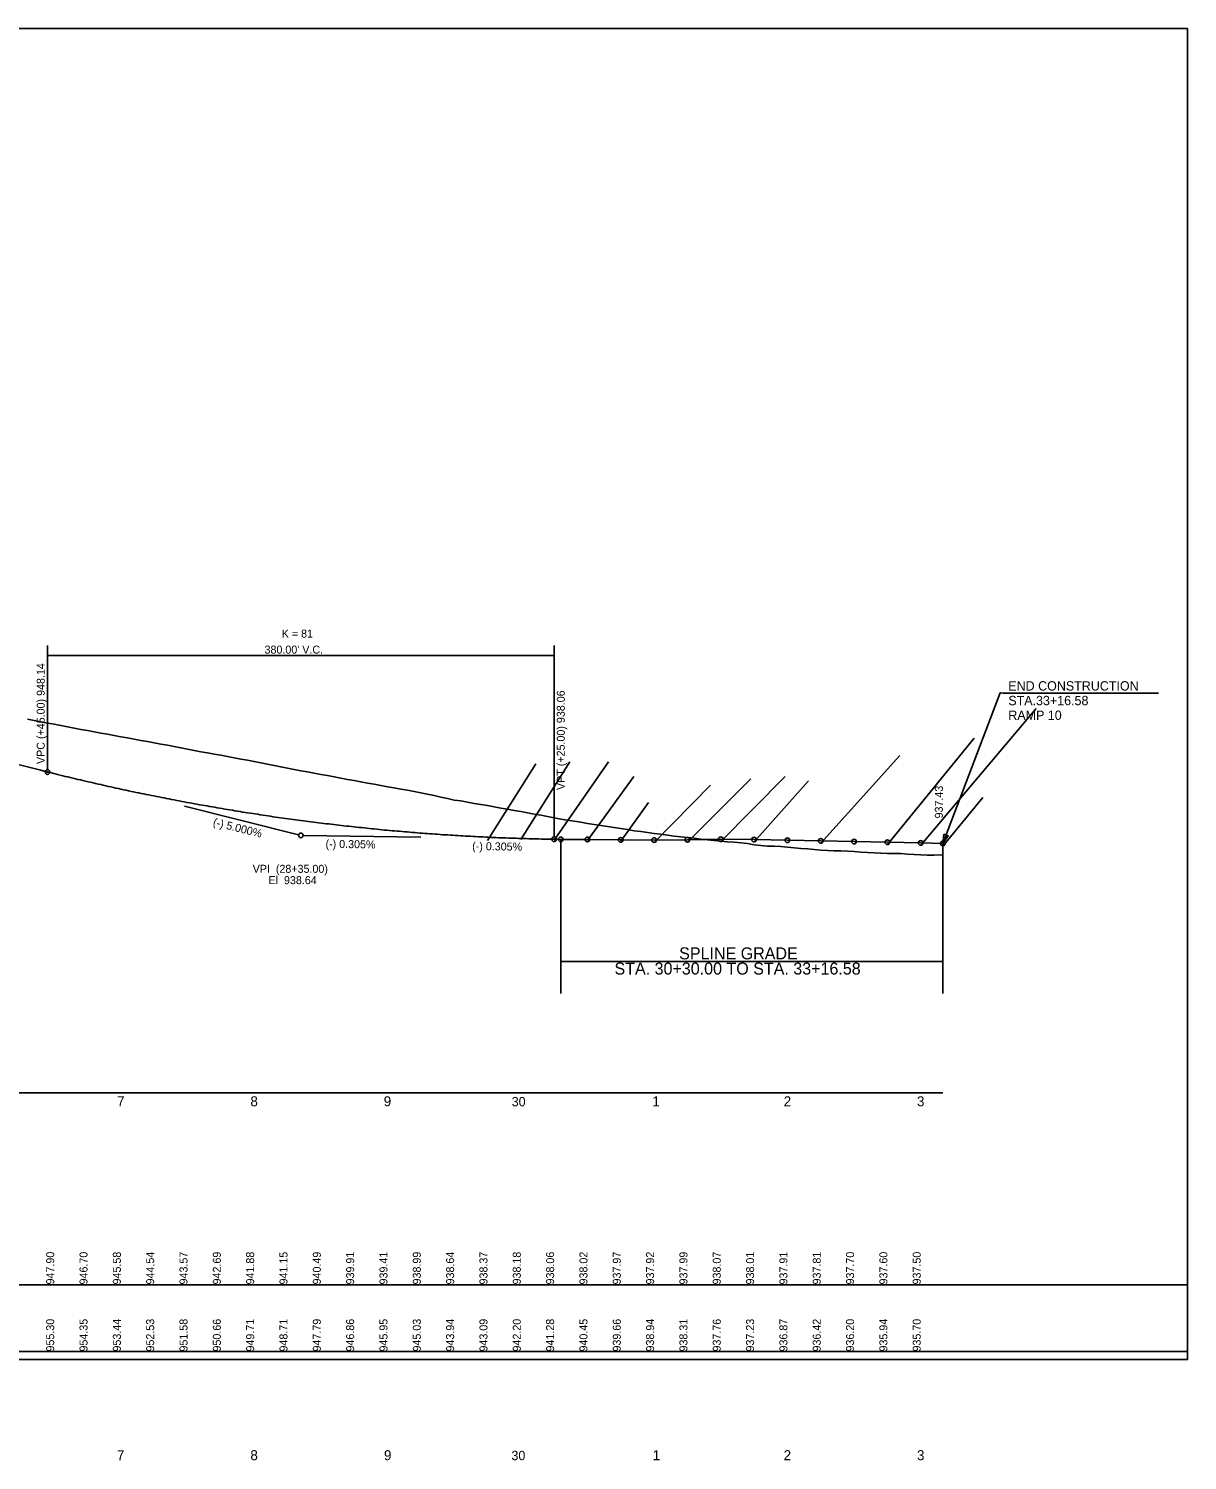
# Model space of a CAD drawing. Extents: x 111 to 16974612, y 6 to 12550779.
# Drawn here: x 16973743 to 16974612, y 12549503 to 12550577 of the extents above; entities that cross this region are included whole.
import ezdxf

# ---------------------------------------------------------------- set-up
doc = ezdxf.new("R2010")
doc.units = 0
for name, color, linetype in [('Default', 7, 'Continuous'), ('RD_DDB_GradeTX', 7, 'Continuous'), ('RD_DDB_PI', 7, 'Continuous'), ('RD_DDB_Profile_EX', 7, 'Continuous'), ('RD_DDB_Profile_Lbl', 7, 'Continuous'), ('RD_DDB_Profile_PR', 7, 'Continuous'), ('RD_DDB_StaTX', 7, 'Continuous'), ('RD_DDB_StripGrade', 7, 'Continuous'), ('RD_DDB_StripGrade_EX', 7, 'Continuous'), ('RD_DDB_StripGrade_PR', 7, 'Continuous'), ('RD_DDB_VCLbl', 7, 'Continuous'), ('RD_GPK_Profile_Cell', 7, 'Continuous'), ('RD_Sketch1', 7, 'Continuous'), ('RD_TX_Profile', 7, 'Continuous')]:
    doc.layers.add(name, color=color, linetype=linetype)

msp = doc.modelspace()

# ---------------------------------------------------------------- linework, layer by layer
at = {"layer": 'Default'}
msp.add_lwpolyline([(16973112.2, 12549578.8), (16974612.2, 12549578.8), (16974612.2, 12550577), (16973112.2, 12550577)], close=True, dxfattribs=at)
at = {"layer": 'RD_DDB_PI'}
for p, q in [((16973859.9, 12549993.8), (16973945.5, 12549972.4)), ((16974037.2, 12549970.6), (16973949, 12549972))]:
    msp.add_line(p, q, dxfattribs=at)
for centre in [(16973947.2, 12549972), (16974142.2, 12549969), (16974162.2, 12549968.9), (16974187.2, 12549968.6), (16974212.2, 12549968.4), (16974237.2, 12549968.7), (16974262.2, 12549969.1), (16974287.2, 12549968.8), (16974312.2, 12549968.3), (16974337.2, 12549967.8), (16974362.2, 12549967.3), (16974387.2, 12549966.8), (16974412.2, 12549966.3), (16974428.8, 12549965.9)]:
    msp.add_circle(centre, 1.75, dxfattribs=at)
at = {"layer": 'RD_DDB_Profile_EX'}
for points in [[(16973742.2, 12550059.1), (16973747.2, 12550058.1), (16973752.2, 12550057.2), (16973757.2, 12550056.2), (16973762.2, 12550055.3), (16973767.2, 12550054.4), (16973772.2, 12550053.4), (16973777.2, 12550052.5), (16973782.2, 12550051.5), (16973787.2, 12550050.6), (16973792.2, 12550049.6), (16973797.2, 12550048.7), (16973802.2, 12550047.8), (16973807.2, 12550046.9), (16973812.2, 12550046), (16973817.2, 12550045.1), (16973822.2, 12550044.1), (16973827.2, 12550043.2), (16973832.2, 12550042.3), (16973837.2, 12550041.4), (16973842.2, 12550040.5), (16973847.2, 12550039.6), (16973852.2, 12550038.6), (16973857.2, 12550037.7), (16973862.2, 12550036.7), (16973867.2, 12550035.7), (16973872.2, 12550034.7), (16973877.2, 12550033.9), (16973882.2, 12550033), (16973887.2, 12550032.1), (16973892.2, 12550031.2), (16973897.2, 12550030.2), (16973902.2, 12550029.2), (16973907.2, 12550028.3), (16973912.2, 12550027.3), (16973917.2, 12550026.4), (16973922.2, 12550025.3), (16973927.2, 12550024.3), (16973932.2, 12550023.3), (16973937.2, 12550022.4), (16973942.2, 12550021.4), (16973947.2, 12550020.5), (16973952.2, 12550019.6), (16973957.2, 12550018.6), (16973962.2, 12550017.7), (16973967.2, 12550016.8), (16973972.2, 12550015.9), (16973977.2, 12550015), (16973982.2, 12550014), (16973987.2, 12550013.1), (16973992.2, 12550012.1), (16973997.2, 12550011.2), (16974002.2, 12550010.3), (16974007.2, 12550009.4), (16974012.2, 12550008.5), (16974017.2, 12550007.7), (16974022.2, 12550006.7), (16974027.2, 12550005.8), (16974032.2, 12550004.9), (16974037.2, 12550003.9), (16974042.2, 12550002.8), (16974047.2, 12550001.8), (16974052.2, 12550000.7), (16974057.2, 12549999.7), (16974062.2, 12549998.5), (16974067.2, 12549997.9), (16974072.2, 12549997), (16974077.2, 12549996), (16974082.2, 12549995.1), (16974087.2, 12549994.3), (16974092.2, 12549993.4), (16974097.2, 12549992.5), (16974102.2, 12549991.6), (16974107.2, 12549990.7), (16974112.2, 12549989.8)], [(16974112.2, 12549989.8), (16974117.2, 12549988.9), (16974122.2, 12549988), (16974127.2, 12549987.1), (16974132.2, 12549986.2), (16974137.2, 12549985.2), (16974142.2, 12549984.2), (16974147.2, 12549983.3), (16974152.2, 12549982.6), (16974157.2, 12549981.8), (16974162.2, 12549981), (16974167.2, 12549980.2), (16974172.2, 12549979.5), (16974177.2, 12549978.7), (16974182.2, 12549977.8), (16974187.2, 12549977.1), (16974192.2, 12549976.3), (16974197.2, 12549975.5), (16974202.2, 12549974.8), (16974207.2, 12549974.2), (16974212.2, 12549973.5), (16974217.2, 12549972.8), (16974222.2, 12549972.1), (16974227.2, 12549971.5), (16974232.2, 12549970.9), (16974237.2, 12549970.3), (16974242.2, 12549969.8), (16974247.2, 12549969.2), (16974252.2, 12549968.7), (16974257.2, 12549968.1), (16974262.2, 12549967.6), (16974267.2, 12549967.2), (16974272.2, 12549966.9), (16974277.2, 12549966.5), (16974282.2, 12549965.8), (16974287.2, 12549965), (16974292.2, 12549964.4), (16974297.2, 12549964), (16974302.2, 12549963.8), (16974307.2, 12549963.6), (16974312.2, 12549963.1), (16974317.2, 12549962.6), (16974322.2, 12549962.2), (16974327.2, 12549961.8), (16974332.2, 12549961.3), (16974337.2, 12549960.9), (16974342.2, 12549960.6), (16974347.2, 12549960.4), (16974352.2, 12549960.3), (16974357.2, 12549960.1), (16974362.2, 12549959.8), (16974367.2, 12549959.4), (16974372.2, 12549959.1), (16974377.2, 12549958.9), (16974382.2, 12549958.6), (16974387.2, 12549958.5), (16974392.2, 12549958.4), (16974397.2, 12549958.3), (16974402.2, 12549958), (16974407.2, 12549957.7), (16974412.2, 12549957.3), (16974417.2, 12549957.1), (16974422.2, 12549957.2), (16974427.2, 12549957.3), (16974428.8, 12549957.2)]]:
    msp.add_lwpolyline(points, dxfattribs=at)
at = {"layer": 'RD_DDB_Profile_Lbl'}
for p, q in [((16973112.2, 12549634.9), (16974612.2, 12549634.9)), ((16973112.2, 12549584.9), (16974612.2, 12549584.9))]:
    msp.add_line(p, q, dxfattribs=at)
at = {"layer": 'RD_DDB_Profile_PR'}
for p, q in [((16973392.2, 12550110.8), (16973762.2, 12550018.3)), ((16973752.2, 12550020.8), (16973757.2, 12550019.5)), ((16974137.2, 12549969.1), (16974142.2, 12549969)), ((16974142.2, 12549969), (16974162.2, 12549968.9)), ((16974162.2, 12549968.9), (16974187.2, 12549968.6)), ((16974187.2, 12549968.6), (16974212.2, 12549968.4)), ((16974212.2, 12549968.4), (16974237.2, 12549968.7)), ((16974237.2, 12549968.7), (16974262.2, 12549969.1)), ((16974262.2, 12549969.1), (16974287.2, 12549968.8)), ((16974287.2, 12549968.8), (16974312.2, 12549968.3)), ((16974312.2, 12549968.3), (16974337.2, 12549967.8)), ((16974337.2, 12549967.8), (16974362.2, 12549967.3)), ((16974362.2, 12549967.3), (16974387.2, 12549966.8)), ((16974387.2, 12549966.8), (16974412.2, 12549966.3)), ((16974412.2, 12549966.3), (16974428.8, 12549965.9))]:
    msp.add_line(p, q, dxfattribs=at)
msp.add_spline([(16973757.2, 12550019.5), (16973764.8, 12550017.6), (16973772.4, 12550015.8), (16973780, 12550014), (16973787.6, 12550012.2), (16973795.2, 12550010.5), (16973802.8, 12550008.7), (16973810.4, 12550007.1), (16973818, 12550005.4), (16973825.6, 12550003.8), (16973833.2, 12550002.3), (16973840.8, 12550000.8), (16973848.4, 12549999.3), (16973856, 12549997.8), (16973863.6, 12549996.4), (16973871.2, 12549995), (16973878.8, 12549993.7), (16973886.4, 12549992.4), (16973894, 12549991.1), (16973901.6, 12549989.8), (16973909.2, 12549988.6), (16973916.8, 12549987.5), (16973924.4, 12549986.3), (16973932, 12549985.2), (16973939.6, 12549984.2), (16973947.2, 12549983.2), (16973954.8, 12549982.2), (16973962.4, 12549981.2), (16973970, 12549980.3), (16973977.6, 12549979.4), (16973985.2, 12549978.6), (16973992.8, 12549977.8), (16974000.4, 12549977), (16974008, 12549976.2), (16974015.6, 12549975.5), (16974023.2, 12549974.9), (16974030.8, 12549974.2), (16974038.4, 12549973.6), (16974046, 12549973.1), (16974053.6, 12549972.5), (16974061.2, 12549972.1), (16974068.8, 12549971.6), (16974076.4, 12549971.2), (16974084, 12549970.8), (16974091.6, 12549970.4), (16974099.2, 12549970.1), (16974106.8, 12549969.9), (16974114.4, 12549969.6), (16974122, 12549969.4), (16974129.6, 12549969.2), (16974137.2, 12549969.1)], degree=3, dxfattribs=at)
at = {"layer": 'RD_DDB_StripGrade'}
for p, q in [((16974142.2, 12549853.3), (16974142.2, 12549969)), ((16974428.8, 12549853.3), (16974428.8, 12549965.9)), ((16974142.2, 12549877.4), (16974428.8, 12549877.4))]:
    msp.add_line(p, q, dxfattribs=at)
at = {"layer": 'RD_DDB_VCLbl'}
for p, q in [((16973757.2, 12550114.5), (16973757.2, 12550021.3)), ((16974137.2, 12550114.5), (16974137.2, 12549970.9)), ((16973757.2, 12550107), (16974137.2, 12550107))]:
    msp.add_line(p, q, dxfattribs=at)
for centre in [(16973757.2, 12550019.5), (16974137.2, 12549969.1), (16974142.2, 12549969)]:
    msp.add_circle(centre, 1.75, dxfattribs=at)
at = {"layer": 'RD_GPK_Profile_Cell'}
msp.add_line((16973112.2, 12549778.8), (16974428.8, 12549778.8), dxfattribs=at)
at = {"layer": 'RD_Sketch1'}
for p, q in [((16974412.2, 12549964.6), (16974498.7, 12550067.2)), ((16974387.2, 12549965.1), (16974452.4, 12550044.8)), ((16974087.2, 12549968.2), (16974123.6, 12550025.6)), ((16974112.2, 12549968.8), (16974149.1, 12550027.2)), ((16974137.2, 12549968.5), (16974177.9, 12550027.2)), ((16974337.2, 12549966.1), (16974396.6, 12550032)), ((16974162.2, 12549968.1), (16974197, 12550016.1)), ((16974237.2, 12549967), (16974284.8, 12550014.5)), ((16974262.2, 12549967.4), (16974310.4, 12550016.1)), ((16974287.2, 12549967.2), (16974327.9, 12550012.9)), ((16974212.2, 12549966.7), (16974254.5, 12550009.7)), ((16974428.8, 12549963.9), (16974458.8, 12550000.5)), ((16974187.2, 12549967.7), (16974207.9, 12549996.6))]:
    msp.add_line(p, q, dxfattribs=at)
at = {"layer": 'RD_TX_Profile'}
msp.add_line((16974590.5, 12550078.6), (16974473.9, 12550078.6), dxfattribs=at)
msp.add_lwpolyline([(16974473.9, 12550078.6), (16974471.9, 12550079), (16974428.8, 12549965.9)], dxfattribs=at)
msp.add_lwpolyline([(16974429.5, 12549972.9), (16974428.8, 12549965.9), (16974432.9, 12549971.6)], close=True, dxfattribs=at)

# ---------------------------------------------------------------- texts
at = {"layer": 'RD_DDB_GradeTX'}
for s, rotation, p in [('(-) 5.000%', 345.9638, (16973880.9, 12549979.3)), ('(-) 0.305%', 359.127, (16973965.7, 12549962.7)), ('(-) 0.305%', 359.127, (16974075.7, 12549961))]:
    msp.add_text(s, height=6, rotation=rotation, dxfattribs=at).set_placement(p)
at = {"layer": 'RD_DDB_PI'}
msp.add_text('937.43', height=6, rotation=90, dxfattribs=at).set_placement((16974428.8, 12549984.7))
for s, p in [('VPI  (28+35.00)', (16973911.1, 12549943.9)), ('El  938.64', (16973923, 12549935.4))]:
    msp.add_text(s, height=6, dxfattribs=at).set_placement(p)
at = {"layer": 'RD_DDB_StaTX'}
for s, height, p in [('7', 7.5, (16973809.4, 12549768.8)), ('8', 7.5, (16973909.4, 12549768.8)), ('9', 7.5, (16974009.4, 12549768.8)), ('30', 7, (16974105.4, 12549768.8)), ('1', 7.5, (16974210.9, 12549768.8)), ('2', 7.5, (16974309.4, 12549768.8)), ('3', 7.5, (16974409.4, 12549768.8)), ('7', 7.5, (16973809.3, 12549503.4)), ('8', 7.5, (16973909.4, 12549503.4)), ('9', 7.5, (16974009.6, 12549503.4)), ('30', 7, (16974105.2, 12549503.4)), ('1', 7.5, (16974211.2, 12549503.4)), ('2', 7.5, (16974309.4, 12549503.4)), ('3', 7.5, (16974409.4, 12549503.4))]:
    msp.add_text(s, height=height, dxfattribs=at).set_placement(p)
at = {"layer": 'RD_DDB_StripGrade'}
for s, p in [('SPLINE GRADE', (16974231, 12549879)), ('STA. 30+30.00 TO STA. 33+16.58', (16974182.5, 12549867.6))]:
    msp.add_text(s, height=9, dxfattribs=at).set_placement(p)
at = {"layer": 'RD_DDB_StripGrade_EX'}
for s, p in [('955.30', (16973762.2, 12549584.9)), ('954.35', (16973787.2, 12549584.9)), ('953.44', (16973812.2, 12549584.9)), ('952.53', (16973837.2, 12549584.9)), ('951.58', (16973862.2, 12549584.9)), ('950.66', (16973887.2, 12549584.9)), ('949.71', (16973912.2, 12549584.9)), ('948.71', (16973937.2, 12549584.9)), ('947.79', (16973962.2, 12549584.9)), ('946.86', (16973987.2, 12549584.9)), ('945.95', (16974012.2, 12549584.9)), ('945.03', (16974037.2, 12549584.9)), ('943.94', (16974062.2, 12549584.9)), ('943.09', (16974087.2, 12549584.9)), ('942.20', (16974112.2, 12549584.9)), ('941.28', (16974137.2, 12549584.9)), ('940.45', (16974162.2, 12549584.9)), ('939.66', (16974187.2, 12549584.9)), ('938.94', (16974212.2, 12549584.9)), ('938.31', (16974237.2, 12549584.9)), ('937.76', (16974262.2, 12549584.9)), ('937.23', (16974287.2, 12549584.9)), ('936.87', (16974312.2, 12549584.9)), ('936.42', (16974337.2, 12549584.9)), ('936.20', (16974362.2, 12549584.9)), ('935.94', (16974387.2, 12549584.9)), ('935.70', (16974412.2, 12549584.9))]:
    msp.add_text(s, height=6, rotation=90, dxfattribs=at).set_placement(p)
at = {"layer": 'RD_DDB_StripGrade_PR'}
for s, p in [('947.90', (16973762.2, 12549635.2)), ('946.70', (16973787.2, 12549635.2)), ('945.58', (16973812.2, 12549635.2)), ('944.54', (16973837.2, 12549635.2)), ('943.57', (16973862.2, 12549635.2)), ('942.69', (16973887.2, 12549635.2)), ('941.88', (16973912.2, 12549635.2)), ('941.15', (16973937.2, 12549635.2)), ('940.49', (16973962.2, 12549635.2)), ('939.91', (16973987.2, 12549635.2)), ('939.41', (16974012.2, 12549635.2)), ('938.99', (16974037.2, 12549635.2)), ('938.64', (16974062.2, 12549635.2)), ('938.37', (16974087.2, 12549635.2)), ('938.18', (16974112.2, 12549635.2)), ('938.06', (16974137.2, 12549635.2)), ('938.02', (16974162.2, 12549635.2)), ('937.97', (16974187.2, 12549635.2)), ('937.92', (16974212.2, 12549635.2)), ('937.99', (16974237.2, 12549635.2)), ('938.07', (16974262.2, 12549635.2)), ('938.01', (16974287.2, 12549635.2)), ('937.91', (16974312.2, 12549635.2)), ('937.81', (16974337.2, 12549635.2)), ('937.70', (16974362.2, 12549635.2)), ('937.60', (16974387.2, 12549635.2)), ('937.50', (16974412.2, 12549635.2))]:
    msp.add_text(s, height=6, rotation=90, dxfattribs=at).set_placement(p)
at = {"layer": 'RD_DDB_VCLbl'}
for s, p in [('K = 81', (16973932.9, 12550120.3)), ("380.00' V.C.", (16973920, 12550108.3))]:
    msp.add_text(s, height=6, dxfattribs=at).set_placement(p)
for s, p in [('VPC (+45.00) 948.14', (16973755.1, 12550025.5)), ('VPT (+25.00) 938.06', (16974145.2, 12550006))]:
    msp.add_text(s, height=6, rotation=90, dxfattribs=at).set_placement(p)
at = {"layer": 'RD_TX_Profile'}
for s, p in [('END CONSTRUCTION', (16974477.9, 12550080.6)), ('STA.33+16.58 ', (16974477.9, 12550069.6)), ('RAMP 10', (16974477.9, 12550058.6))]:
    msp.add_text(s, height=7, dxfattribs=at).set_placement(p)

doc.saveas('drawing.dxf')
